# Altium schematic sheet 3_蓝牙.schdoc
size 309 x 223 mm; Symbol: Sheet-Symbol_A4; Device: Sheet-Symbol_A4; Company: 嘉立创EDA; Version: V1.0; Page Size: A4; @Project Name: 共享电动车中控; @Page Count: 11; @Update Date: 2024-11-20; @Create Date: 2024-09-10; @Schematic Name: SCH; @Page No: 3; @Page Name: 蓝牙; @Board Name: STM32F103C8T6; @Create Time: 13:12:35; @Update Time: 23:29:15
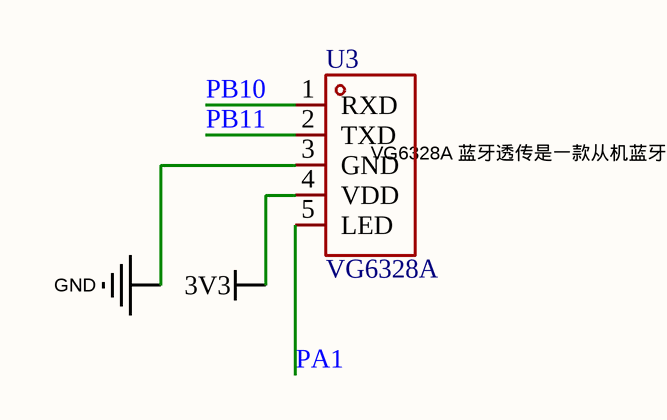
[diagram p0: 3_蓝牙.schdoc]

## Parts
U3  VG6328A  [COMM-SMD_VG6328A]  (value not drawn)

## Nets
3V3: U3.4(VDD)
GND: U3.3(GND)
PA1: U3.5(LED)
PB10: U3.1(RXD)
PB11: U3.2(TXD)

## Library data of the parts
U3 = VG6328A: VG6328A 蓝牙透传是一款从机蓝牙透传模块。; Manufacturer: Vollgo(沃进); Add into BOM: yes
